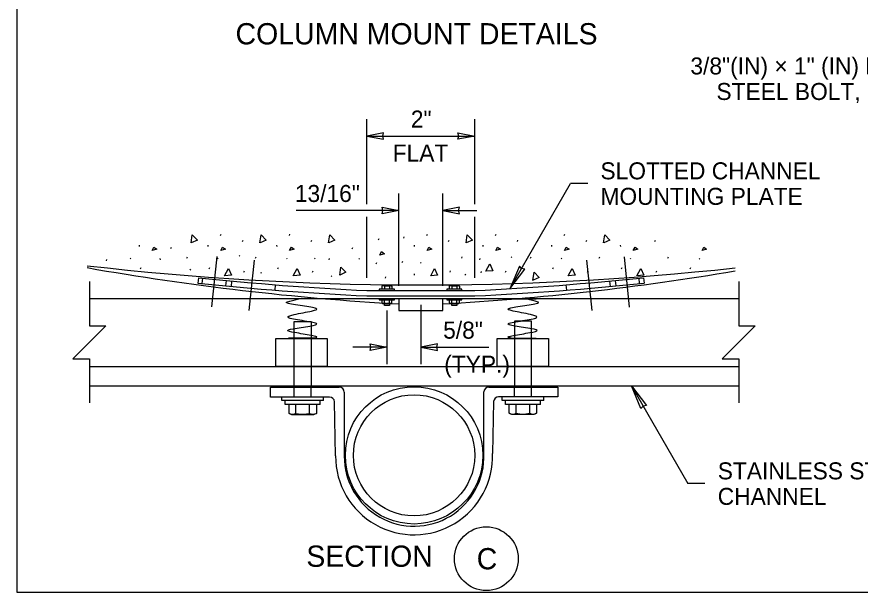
# Model space of a CAD drawing. Extents: x 99862 to 103680, y 99470 to 102076.
# Drawn here: x 99862 to 100655, y 100000 to 100541 of the extents above; entities that cross this region are included whole.
import ezdxf

# ---------------------------------------------------------------- set-up
doc = ezdxf.new("R2010")
doc.units = 0
for name, color, linetype in [('Level 1', 7, 'Continuous'), ('Level 10', 7, 'Continuous'), ('Level 11', 7, 'Continuous'), ('Level 13', 7, 'Continuous'), ('Level 14', 7, 'Continuous'), ('Level 15', 7, 'Continuous'), ('Level 2', 7, 'Continuous'), ('Level 20', 7, 'Continuous'), ('Level 3', 7, 'Continuous'), ('Level 4', 7, 'Continuous'), ('Level 5', 7, 'Continuous'), ('Level 6', 7, 'Continuous'), ('Level 60', 7, 'Continuous'), ('Level 7', 7, 'Continuous'), ('Level 8', 7, 'Continuous'), ('Level 9', 7, 'Continuous')]:
    doc.layers.add(name, color=color, linetype=linetype)

msp = doc.modelspace()

# ---------------------------------------------------------------- linework, layer by layer
at = {"layer": 'Level 1'}
for p, q in [((99930.23, 100275.68), (100540.46, 100275.68)), ((99930.23, 100211.87), (100540.45, 100211.87)), ((99930.23, 100193.41), (100540.46, 100193.41))]:
    msp.add_line(p, q, dxfattribs=at)
msp.add_lwpolyline([(99862, 99999.5), (103151, 99999.5), (103151, 102075.5), (99862, 102075.5)], close=True, dxfattribs=at)
at = {"layer": 'Level 10'}
msp.add_arc((100241.68, 103022.2), 2733.75, 263.41476, 276.20356, dxfattribs=at)
at = {"layer": 'Level 11'}
for p, q in [((100053.53, 100334.84), (100054.07, 100336.06)), ((100074.03, 100329.31), (100074.57, 100330.53)), ((100118.14, 100334.84), (100118.68, 100336.06)), ((100138.64, 100329.31), (100139.18, 100330.53)), ((100201.89, 100330.98), (100202.43, 100332.2)), ((100225.61, 100332.41), (100226.15, 100333.63)), ((100247.35, 100334.84), (100247.89, 100336.06)), ((100267.85, 100329.31), (100268.39, 100330.53)), ((100311.95, 100334.84), (100312.49, 100336.06)), ((100332.45, 100329.31), (100332.99, 100330.53)), ((100376.55, 100334.84), (100377.09, 100336.06)), ((100397.05, 100329.31), (100397.59, 100330.53)), ((100461.66, 100329.31), (100462.2, 100330.53)), ((99976.89, 100325.93), (99977.03, 100324.71)), ((100006.86, 100322.83), (100007.4, 100324.04)), ((100041.5, 100325.93), (100041.63, 100324.71)), ((100106.1, 100325.93), (100106.23, 100324.71)), ((100177.13, 100322.4), (100177.67, 100323.62)), ((100235.31, 100325.93), (100235.44, 100324.71)), ((100299.91, 100325.93), (100300.05, 100324.71)), ((100364.51, 100325.93), (100364.65, 100324.71)), ((100429.12, 100325.93), (100429.25, 100324.71)), ((99968.59, 100313.67), (99969.13, 100312.86)), ((99996.52, 100313.23), (99996.65, 100312.02)), ((100021.7, 100313.67), (100022.24, 100314.88)), ((100050.7, 100313.67), (100051.24, 100312.86)), ((100071.08, 100316.21), (100071.62, 100315.4)), ((100086.31, 100313.67), (100086.85, 100314.88)), ((100115.31, 100313.67), (100115.84, 100312.86)), ((100141.91, 100313.67), (100142.45, 100312.86)), ((100155.41, 100311.97), (100155.95, 100313.18)), ((100183.5, 100313.36), (100184.04, 100312.55)), ((100280.12, 100313.67), (100280.66, 100314.88)), ((100297.08, 100312.03), (100297.61, 100313.25)), ((100326.75, 100314.94), (100327.29, 100314.13)), ((100344.72, 100313.67), (100345.26, 100314.88)), ((100373.72, 100313.67), (100374.26, 100312.86)), ((100409.33, 100313.67), (100409.87, 100314.88)), ((100438.32, 100313.67), (100438.86, 100312.86)), ((100473.93, 100313.67), (100474.47, 100314.88)), ((100503.47, 100313.36), (100504.01, 100312.55)), ((99946.18, 100311.04), (99946.72, 100312.25)), ((100199.74, 100308.28), (100200.28, 100309.5)), ((100224.31, 100309.63), (100224.85, 100310.84)), ((100241.43, 100309.65), (100241.97, 100308.84)), ((99978.14, 100303.67), (99978.68, 100304.89)), ((100024.85, 100302.17), (100025.39, 100303.39)), ((100042.74, 100303.67), (100043.28, 100304.89)), ((100075.38, 100300.57), (100075.92, 100301.78)), ((100091.2, 100300.33), (100091.74, 100299.52)), ((100107.35, 100303.67), (100107.89, 100304.89)), ((100139.99, 100300.57), (100140.53, 100301.78)), ((100235.31, 100298.91), (100235.44, 100297.7)), ((100269.19, 100300.57), (100269.73, 100301.78)), ((100283.09, 100298.42), (100283.63, 100297.61)), ((100298.32, 100299.92), (100298.86, 100301.13)), ((100321.24, 100300.57), (100321.78, 100301.78)), ((100365.76, 100303.67), (100366.3, 100304.89)), ((100398.4, 100300.57), (100398.94, 100301.78)), ((100430.37, 100303.67), (100430.91, 100304.89)), ((100463.01, 100300.57), (100463.55, 100301.78)), ((100494.97, 100303.67), (100495.51, 100304.89)), ((100157.5, 100297.12), (100158.04, 100296.31)), ((100208.38, 100294.92), (100208.92, 100296.13))]:
    msp.add_line(p, q, dxfattribs=at)
for points in [[(100025.84, 100327.92), (100026.91, 100335.63), (100031.74, 100330.64), (100025.96, 100327.96)], [(100090.44, 100327.92), (100091.51, 100335.63), (100096.34, 100330.64), (100090.57, 100327.96)], [(100155.05, 100327.92), (100156.12, 100335.63), (100160.94, 100330.64), (100155.17, 100327.96)], [(100284.25, 100327.92), (100285.32, 100335.63), (100290.15, 100330.64), (100284.38, 100327.96)], [(100413.46, 100327.92), (100414.53, 100335.63), (100419.36, 100330.64), (100413.59, 100327.96)], [(99989.2, 100320.68), (99990.82, 100324.05), (99993.52, 100322.03), (99989.2, 100320.68)], [(100053.8, 100320.68), (100055.42, 100324.05), (100058.12, 100322.03), (100053.8, 100320.68)], [(100118.41, 100320.68), (100120.03, 100324.05), (100122.72, 100322.03), (100118.41, 100320.68)], [(100247.62, 100320.68), (100249.23, 100324.05), (100251.93, 100322.03), (100247.62, 100320.68)], [(100312.22, 100320.68), (100313.84, 100324.05), (100316.54, 100322.03), (100312.22, 100320.68)], [(100376.82, 100320.68), (100378.44, 100324.05), (100381.14, 100322.03), (100376.82, 100320.68)], [(100441.43, 100320.68), (100443.05, 100324.05), (100445.74, 100322.03), (100441.43, 100320.68)], [(100506.03, 100320.68), (100507.65, 100324.05), (100510.35, 100322.03), (100506.03, 100320.68)], [(100203.2, 100316.43), (100204.81, 100319.8), (100207.51, 100317.78), (100203.2, 100316.43)], [(100165.43, 100297.59), (100166.5, 100305.3), (100171.33, 100300.31), (100165.56, 100297.64)], [(100302.79, 100301.26), (100306.43, 100308.14), (100309.26, 100301.8), (100302.92, 100301.26)], [(100057.18, 100296.93), (100060.82, 100303.81), (100063.65, 100297.47), (100057.31, 100296.93)], [(100121.78, 100296.93), (100125.42, 100303.81), (100128.25, 100297.47), (100121.91, 100296.93)], [(100250.99, 100296.93), (100254.63, 100303.81), (100257.46, 100297.47), (100251.12, 100296.93)], [(100347.07, 100292.73), (100348.14, 100300.44), (100352.97, 100295.45), (100347.2, 100292.78)], [(100380.2, 100296.93), (100383.84, 100303.81), (100386.67, 100297.47), (100380.33, 100296.93)], [(100444.8, 100296.93), (100448.44, 100303.81), (100451.27, 100297.47), (100444.93, 100296.93)]]:
    msp.add_lwpolyline(points, dxfattribs=at)
at = {"layer": 'Level 13'}
for p, q in [((100032.59, 100295.25), (100032.06, 100290.22)), ((100036.27, 100289.78), (100036.79, 100294.81)), ((100058.41, 100287.56), (100058.89, 100292.6)), ((100063.73, 100287.05), (100064.21, 100292.09)), ((100419.83, 100287.06), (100419.34, 100292.1)), ((100425.15, 100287.57), (100424.66, 100292.61)), ((100447.29, 100289.78), (100446.77, 100294.82)), ((100450.97, 100295.26), (100451.49, 100290.22)), ((100104.71, 100283.52), (100105.11, 100288.57)), ((100191.01, 100283.16), (100292.31, 100283.16)), ((100378.85, 100283.53), (100378.45, 100288.58)), ((100191.01, 100278.1), (100292.42, 100278.1)), ((100221.11, 100275.68), (100221.11, 100264.39)), ((100262.25, 100264.39), (100262.25, 100275.68)), ((100221.11, 100264.39), (100262.25, 100264.39))]:
    msp.add_line(p, q, dxfattribs=at)
for centre, radius, start, end in [((100319.64, 103013.89), 2738.81, 263.97284, 267.30815), ((100319.64, 103013.89), 2733.75, 263.97267, 267.30815), ((100163.92, 103013.89), 2733.75, 272.69185, 276.02733), ((100163.92, 103013.89), 2738.81, 272.68936, 276.02716)]:
    msp.add_arc(centre, radius, start, end, dxfattribs=at)
at = {"layer": 'Level 14'}
for centre, start, end in [((100360.44, 102742.88), 259.94747, 266.77447), ((100122.4, 102742.88), 273.23769, 279.63987)]:
    msp.add_arc(centre, 2476.22, start, end, dxfattribs=at)
at = {"layer": 'Level 15'}
for p, q in [((100191.01, 100364.46), (100191.01, 100444.46)), ((100292.31, 100364.46), (100292.31, 100444.46)), ((100191.01, 100428.46), (100292.31, 100428.46)), ((100325.46, 100284.92), (100382.52, 100383.75)), ((100398.52, 100383.75), (100382.52, 100383.75)), ((100221.11, 100287.68), (100221.11, 100374.46)), ((100262.25, 100287.68), (100262.25, 100374.46)), ((100221.11, 100358.46), (100124.51, 100358.46)), ((100262.25, 100358.46), (100294.25, 100358.46)), ((100191.01, 100295.16), (100191.01, 100352.46)), ((100292.31, 100295.16), (100292.31, 100352.46)), ((100045.27, 100267.98), (100050.19, 100315.28)), ((100437.97, 100267.67), (100433.05, 100314.97)), ((100080.39, 100264.28), (100085.31, 100311.58)), ((100402.69, 100264.52), (100397.77, 100311.81)), ((100241.68, 100269.62), (100241.68, 100213.9)), ((100209.8, 100264.39), (100209.8, 100213.9)), ((100209.8, 100229.9), (100177.8, 100229.9)), ((100241.68, 100229.9), (100305.68, 100229.9)), ((100439.74, 100193.41), (100492.77, 100101.57)), ((100508.77, 100101.57), (100492.77, 100101.57))]:
    msp.add_line(p, q, dxfattribs=at)
for points in [[(100191.01, 100428.46), (100206.74, 100425.38), (100206.01, 100428.46), (100206.74, 100431.55)], [(100292.31, 100428.46), (100276.58, 100425.38), (100277.31, 100428.46), (100276.58, 100431.55)], [(100221.11, 100358.46), (100205.39, 100355.38), (100206.11, 100358.46), (100205.39, 100361.55)], [(100262.25, 100358.46), (100277.97, 100355.38), (100277.25, 100358.46), (100277.97, 100361.55)], [(100325.46, 100284.92), (100339.46, 100303.2), (100336.35, 100303.78), (100334.29, 100306.19)], [(100209.8, 100229.9), (100194.07, 100226.82), (100194.8, 100229.9), (100194.07, 100232.99)], [(100241.68, 100229.9), (100257.41, 100226.82), (100256.68, 100229.9), (100257.41, 100232.99)], [(100439.74, 100193.41), (100453.74, 100175.14), (100450.63, 100174.56), (100448.57, 100172.15)]]:
    msp.add_lwpolyline(points, close=True, dxfattribs=at)
for points in [[(99930.23, 100291.68), (99930.23, 100250.03), (99945.71, 100250.03), (99914.74, 100219.06), (99930.23, 100219.06), (99930.23, 100177.41)], [(100540.46, 100291.68), (100540.46, 100250.03), (100555.94, 100250.03), (100524.97, 100219.06), (100540.46, 100219.06), (100540.46, 100177.41)]]:
    msp.add_lwpolyline(points, dxfattribs=at)
at = {"layer": 'Level 2'}
for p, q in [((100100.35, 100183.02), (100100.35, 100192.25)), ((100100.35, 100192.25), (100165.06, 100192.25)), ((100122.56, 100183.03), (100122.56, 100192.25)), ((100138.71, 100183.03), (100138.71, 100192.25)), ((100169.67, 100187.64), (100169.67, 100127.57)), ((100301.01, 100129.62), (100301.01, 100187.79)), ((100305.62, 100192.4), (100370.34, 100192.4)), ((100329.6, 100183.17), (100329.6, 100192.4)), ((100345.75, 100183.17), (100345.75, 100192.4)), ((100370.34, 100192.4), (100370.34, 100183.17)), ((100155.91, 100183.02), (100100.35, 100183.02)), ((100161.55, 100127.61), (100160.53, 100178.5)), ((100310.15, 100178.65), (100309.12, 100129.91)), ((100370.34, 100183.17), (100314.76, 100183.17))]:
    msp.add_line(p, q, dxfattribs=at)
for centre, radius, start, end in [((100165.06, 100187.64), 4.61, 0, 90), ((100305.62, 100187.79), 4.61, 90, 180), ((100155.91, 100178.41), 4.61, 1.0465, 90), ((100314.76, 100178.56), 4.61, 90, 178.90969), ((100235.36, 100127.24), 73.81, 179.71144, 2.07797), ((100235.36, 100127.24), 65.69, 179.71144, 2.07797)]:
    msp.add_arc(centre, radius, start, end, dxfattribs=at)
at = {"layer": 'Level 20'}
msp.add_circle((100303.27, 100030.94), 30, dxfattribs=at)
at = {"layer": 'Level 3'}
for points in [[(100105.31, 100238), (100153.66, 100238), (100153.66, 100211.87), (100105.31, 100211.87)], [(100313.5, 100238), (100361.85, 100238), (100361.85, 100211.87), (100313.5, 100211.87)]]:
    msp.add_lwpolyline(points, close=True, dxfattribs=at)
at = {"layer": 'Level 4'}
for p, q in [((100122.56, 100193.41), (100122.56, 100254.15)), ((100122.56, 100254.15), (100138.71, 100254.15)), ((100138.71, 100254.15), (100138.71, 100193.41)), ((100345.75, 100254.3), (100329.6, 100254.3)), ((100329.6, 100254.3), (100329.6, 100193.56)), ((100345.75, 100193.56), (100345.75, 100254.3)), ((100117.79, 100167.67), (100117.79, 100175.93)), ((100124.21, 100167.67), (100124.21, 100175.93)), ((100137.06, 100167.67), (100137.06, 100175.93)), ((100143.49, 100175.93), (100143.49, 100167.67)), ((100324.82, 100167.81), (100324.82, 100176.07)), ((100331.25, 100167.81), (100331.25, 100176.07)), ((100344.1, 100167.81), (100344.1, 100176.07)), ((100350.52, 100176.07), (100350.52, 100167.81)), ((100120.36, 100166.29), (100117.79, 100167.67)), ((100140.92, 100166.29), (100120.36, 100166.29)), ((100143.49, 100167.67), (100140.92, 100166.29)), ((100327.39, 100166.43), (100324.82, 100167.81)), ((100347.95, 100166.43), (100327.39, 100166.43)), ((100350.52, 100167.81), (100347.95, 100166.43))]:
    msp.add_line(p, q, dxfattribs=at)
for points in [[(100117.79, 100167.67), (100118.84, 100167.1), (100119.91, 100166.74), (100122.09, 100166.74), (100123.16, 100167.1), (100124.21, 100167.67)], [(100124.21, 100167.67), (100125.26, 100167.39), (100126.31, 100167.15), (100128.45, 100166.83), (100129.55, 100166.74), (100132.81, 100166.74), (100134.96, 100167.1), (100137.06, 100167.67)], [(100137.06, 100167.67), (100138.12, 100167.1), (100139.18, 100166.74), (100141.36, 100166.74), (100142.44, 100167.1), (100143.49, 100167.67)], [(100324.82, 100167.81), (100325.88, 100167.25), (100326.94, 100166.89), (100329.12, 100166.89), (100330.2, 100167.25), (100331.25, 100167.81)], [(100331.25, 100167.81), (100332.29, 100167.53), (100333.34, 100167.3), (100335.48, 100166.98), (100336.58, 100166.89), (100339.84, 100166.89), (100342, 100167.25), (100344.1, 100167.81)], [(100344.1, 100167.81), (100345.15, 100167.25), (100346.22, 100166.89), (100348.4, 100166.89), (100349.47, 100167.25), (100350.52, 100167.81)]]:
    msp.add_open_spline(points, degree=3, dxfattribs=at)
at = {"layer": 'Level 5'}
for p, q in [((100150.23, 100179.74), (100111.05, 100179.74)), ((100357.27, 100179.89), (100318.08, 100179.89))]:
    msp.add_line(p, q, dxfattribs=at)
for points in [[(100111.05, 100179.74), (100111.05, 100183.03)], [(100150.23, 100179.74), (100150.23, 100183.03)], [(100318.08, 100179.89), (100318.08, 100183.17)], [(100357.27, 100179.89), (100357.27, 100183.17)]]:
    msp.add_lwpolyline(points, dxfattribs=at)
at = {"layer": 'Level 6'}
for p, q in [((100147.05, 100175.93), (100114.23, 100175.93)), ((100354.09, 100176.07), (100321.26, 100176.07))]:
    msp.add_line(p, q, dxfattribs=at)
for points in [[(100114.23, 100175.93), (100114.23, 100179.74)], [(100147.05, 100175.93), (100147.05, 100179.74)], [(100321.26, 100176.07), (100321.26, 100179.89)], [(100354.09, 100176.07), (100354.09, 100179.89)]]:
    msp.add_lwpolyline(points, dxfattribs=at)
at = {"layer": 'Level 60'}
msp.add_line((99862, 99999.5), (99862, 99999.5), dxfattribs=at)
at = {"layer": 'Level 7'}
for p, q in [((100142.7, 100275.27), (100117.39, 100275.27)), ((100324.8, 100275.27), (100350.12, 100275.27)), ((100142.7, 100238.36), (100117.39, 100238.36)), ((100324.8, 100238.36), (100350.12, 100238.36))]:
    msp.add_line(p, q, dxfattribs=at)
for points in [[(100140.77, 100238.36), (100140.86, 100238.38), (100144.01, 100239), (100144.64, 100239.95), (100125.9, 100243.11), (100113.91, 100245.15), (100119.53, 100247.21), (100138.93, 100249.73), (100148.04, 100251.85), (100129.83, 100254.93), (100113.09, 100257.64), (100120.44, 100260.44), (100141.78, 100264.18), (100146.6, 100266.21), (100130.74, 100268.65), (100112.47, 100271.57), (100116.92, 100272.84), (100126.01, 100275.05), (100127.08, 100275.27)], [(100326.74, 100238.36), (100326.65, 100238.38), (100323.49, 100239), (100322.87, 100239.95), (100341.61, 100243.11), (100353.6, 100245.15), (100347.98, 100247.21), (100328.58, 100249.73), (100319.47, 100251.85), (100337.68, 100254.93), (100354.41, 100257.64), (100347.07, 100260.44), (100325.73, 100264.18), (100320.91, 100266.21), (100336.77, 100268.65), (100355.04, 100271.57), (100350.58, 100272.84), (100341.5, 100275.05), (100340.43, 100275.27)]]:
    msp.add_open_spline(points, degree=3, dxfattribs=at)
at = {"layer": 'Level 8'}
for p, q in [((100216.91, 100284.35), (100202.68, 100284.35)), ((100202.68, 100284.35), (100202.68, 100283.16)), ((100205.05, 100287.4), (100206, 100287.91)), ((100205.05, 100287.4), (100205.05, 100284.35)), ((100206, 100287.91), (100213.59, 100287.91)), ((100207.42, 100287.4), (100207.42, 100284.35)), ((100212.17, 100287.4), (100212.17, 100284.35)), ((100213.59, 100287.91), (100214.54, 100287.4)), ((100214.54, 100287.4), (100214.54, 100284.35)), ((100216.91, 100283.16), (100216.91, 100284.35)), ((100280.33, 100284.35), (100266.09, 100284.35)), ((100266.09, 100284.35), (100266.09, 100283.16)), ((100268.46, 100287.4), (100269.41, 100287.91)), ((100268.46, 100287.4), (100268.46, 100284.35)), ((100269.41, 100287.91), (100277, 100287.91)), ((100270.83, 100287.4), (100270.83, 100284.35)), ((100275.58, 100287.4), (100275.58, 100284.35)), ((100277, 100287.91), (100277.95, 100287.4)), ((100277.95, 100287.4), (100277.95, 100284.35)), ((100280.33, 100283.16), (100280.33, 100284.35)), ((100202.68, 100275.69), (100202.68, 100274.51)), ((100202.68, 100274.51), (100216.91, 100274.51)), ((100205.05, 100274.51), (100205.05, 100271.45)), ((100207.42, 100271.45), (100207.42, 100274.51)), ((100212.17, 100271.45), (100212.17, 100274.51)), ((100214.54, 100271.45), (100214.54, 100274.51)), ((100216.91, 100274.51), (100216.91, 100275.69)), ((100266.09, 100275.69), (100266.09, 100274.51)), ((100266.09, 100274.51), (100280.33, 100274.51)), ((100268.46, 100274.51), (100268.46, 100271.45)), ((100270.83, 100271.45), (100270.83, 100274.51)), ((100275.58, 100271.45), (100275.58, 100274.51)), ((100277.95, 100271.45), (100277.95, 100274.51)), ((100280.33, 100274.51), (100280.33, 100275.69)), ((100205.05, 100271.45), (100206, 100270.95)), ((100206, 100270.95), (100213.59, 100270.95)), ((100207.42, 100268.95), (100207.42, 100270.95)), ((100212.17, 100268.95), (100207.42, 100268.95)), ((100212.17, 100270.95), (100212.17, 100268.95)), ((100213.59, 100270.95), (100214.54, 100271.45)), ((100268.46, 100271.45), (100269.41, 100270.95)), ((100269.41, 100270.95), (100277, 100270.95)), ((100270.83, 100268.95), (100270.83, 100270.95)), ((100275.58, 100268.95), (100270.83, 100268.95)), ((100275.58, 100270.95), (100275.58, 100268.95)), ((100277, 100270.95), (100277.95, 100271.45))]:
    msp.add_line(p, q, dxfattribs=at)
for points, degree in [([(100207.42, 100287.4), (100207.03, 100287.61), (100206.64, 100287.74), (100205.83, 100287.74), (100205.44, 100287.61), (100205.05, 100287.4)], 3), ([(100205.05, 100287.4), (100205.05, 100287.4), (100205.05, 100287.4), (100205.05, 100287.4)], 2), ([(100207.42, 100287.4), (100208.2, 100287.61), (100209, 100287.74), (100210.2, 100287.74), (100210.6, 100287.71), (100211.4, 100287.59), (100211.78, 100287.5), (100212.17, 100287.4)], 3), ([(100214.54, 100287.4), (100214.15, 100287.61), (100213.76, 100287.74), (100212.95, 100287.74), (100212.56, 100287.61), (100212.17, 100287.4)], 3), ([(100214.54, 100287.4), (100214.54, 100287.4), (100214.54, 100287.4), (100214.54, 100287.4)], 2), ([(100270.83, 100287.4), (100270.45, 100287.61), (100270.05, 100287.74), (100269.25, 100287.74), (100268.85, 100287.61), (100268.46, 100287.4)], 3), ([(100268.46, 100287.4), (100268.46, 100287.4), (100268.46, 100287.4), (100268.46, 100287.4)], 2), ([(100270.83, 100287.4), (100271.61, 100287.61), (100272.41, 100287.74), (100273.61, 100287.74), (100274.02, 100287.71), (100274.81, 100287.59), (100275.2, 100287.5), (100275.58, 100287.4)], 3), ([(100277.95, 100287.4), (100277.57, 100287.61), (100277.17, 100287.74), (100276.37, 100287.74), (100275.97, 100287.61), (100275.58, 100287.4)], 3), ([(100277.95, 100287.4), (100277.95, 100287.4), (100277.95, 100287.4), (100277.95, 100287.4)], 2), ([(100205.05, 100271.45), (100205.44, 100271.25), (100205.83, 100271.11), (100206.64, 100271.11), (100207.03, 100271.25), (100207.42, 100271.45)], 3), ([(100207.42, 100271.45), (100208.2, 100271.25), (100209, 100271.11), (100210.2, 100271.11), (100210.6, 100271.15), (100211.4, 100271.27), (100211.78, 100271.35), (100212.17, 100271.45)], 3), ([(100212.17, 100271.45), (100212.56, 100271.25), (100212.95, 100271.11), (100213.76, 100271.11), (100214.15, 100271.25), (100214.54, 100271.45)], 3), ([(100268.46, 100271.45), (100268.85, 100271.25), (100269.25, 100271.11), (100270.05, 100271.11), (100270.45, 100271.25), (100270.83, 100271.45)], 3), ([(100270.83, 100271.45), (100271.61, 100271.25), (100272.41, 100271.11), (100273.61, 100271.11), (100274.02, 100271.15), (100274.81, 100271.27), (100275.2, 100271.35), (100275.58, 100271.45)], 3), ([(100275.58, 100271.45), (100275.97, 100271.25), (100276.37, 100271.11), (100277.17, 100271.11), (100277.57, 100271.25), (100277.95, 100271.45)], 3)]:
    msp.add_open_spline(points, degree=degree, dxfattribs=at)
at = {"layer": 'Level 9'}
for radius in [64.58, 57.02]:
    msp.add_circle((100235.34, 100128.17), radius, dxfattribs=at)

# ---------------------------------------------------------------- texts
at = {"layer": 'Level 20'}
for s, height, p in [('COLUMN MOUNT DETAILS', 20, (100067.54, 100514.66)), ('3/8"(IN) × 1" (IN) LONG STAINLESS ', 16, (100495.07, 100486.38)), ('STEEL BOLT, 2 FLAT WASHERS', 16, (100519.55, 100462.38)), ('2"', 16, (100232.29, 100436.46)), ('FLAT', 16, (100215.24, 100404.46)), ('13/16"', 16, (100123.28, 100366.46)), ('SECTION', 20, (100134.08, 100023.32)), ('C', 20, (100294.21, 100020.94))]:
    msp.add_text(s, height=height, dxfattribs=at).set_placement(p)
for s, p in [('SLOTTED CHANNEL', (100410.52, 100387.75)), ('MOUNTING PLATE', (100410.52, 100363.75)), ('5/8"', (100262.68, 100237.9)), ('(TYP.)', (100263.68, 100205.9)), ('STAINLESS STEEL', (100520.77, 100105.57)), ('CHANNEL', (100520.77, 100081.57))]:
    msp.add_text(s, height=16, rotation=360, dxfattribs=at).set_placement(p)

doc.saveas('drawing.dxf')
